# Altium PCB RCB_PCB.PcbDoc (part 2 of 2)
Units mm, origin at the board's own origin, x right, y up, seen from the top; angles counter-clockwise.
Board outline 360 x 80 mm, 2 copper layers (Top Layer, Bottom Layer); 41 components, 10 nets, 166 pads, 2592 vias.
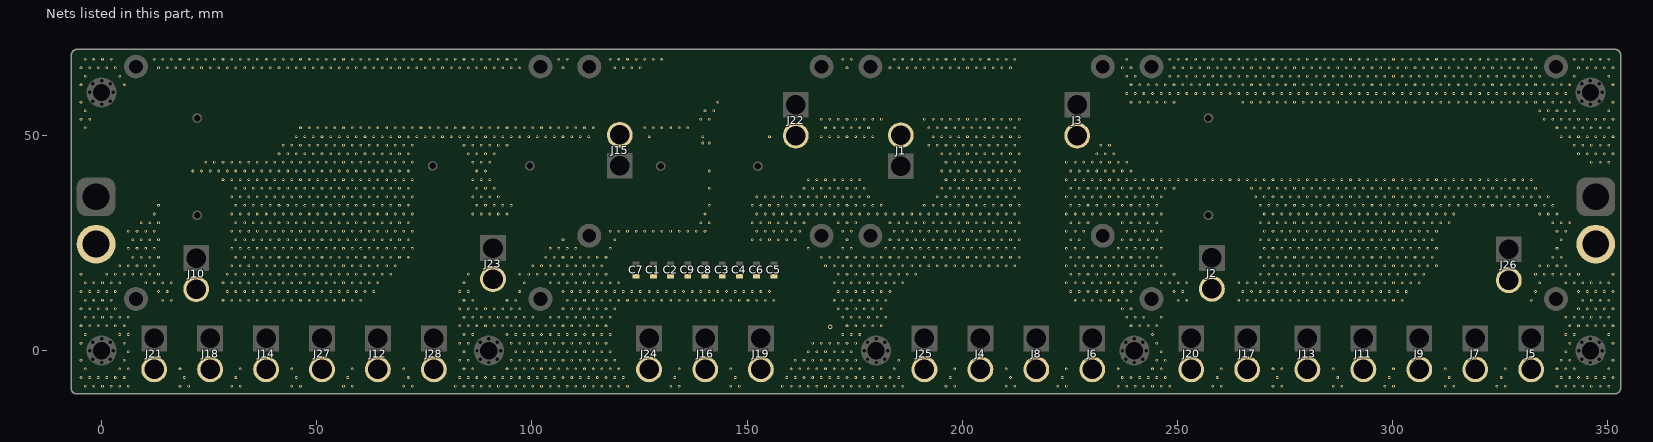
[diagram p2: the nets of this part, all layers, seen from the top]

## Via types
v1: diameter 0.6, hole 0.3, Top Layer to Bottom Layer, tented both sides, 2592 vias

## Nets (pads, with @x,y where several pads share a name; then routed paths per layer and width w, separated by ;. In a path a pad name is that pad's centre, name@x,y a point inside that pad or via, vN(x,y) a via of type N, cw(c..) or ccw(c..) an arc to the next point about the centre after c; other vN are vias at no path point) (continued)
GND: C1.2 C2.2 C3.2 C4.2 C5.2 C6.2 C7.2 C8.2 C9.2 J1.N J2.N J3.N J4.N J5.N J6.N J7.N J8.N J9.N J10.N J11.N J12.N J13.N J14.N J15.N J16.N J17.N J18.N J19.N J20.N J21.N J22.N J23.N J24.N J25.N J26.N J27.N J28.N pad.12 pad.N
  other v1: -3.769,-8.248 -1.769,-8.248 0.231,-8.248 2.231,-8.248 4.231,-8.248 6.231,-8.248 18.231,-8.248 20.231,-8.248 30.231,-8.248 32.231,-8.248 44.231,-8.248 46.231,-8.248 56.231,-8.248 58.231,-8.248 70.231,-8.248 72.231,-8.248 82.231,-8.248 84.231,-8.248 86.231,-8.248 88.231,-8.248 90.231,-8.248 92.231,-8.248 94.231,-8.248 96.231,-8.248 98.231,-8.248 100.231,-8.248 102.231,-8.248 104.231,-8.248 106.231,-8.248 108.231,-8.248 110.231,-8.248 112.231,-8.248 114.231,-8.248 116.231,-8.248 118.231,-8.248 120.231,-8.248 122.231,-8.248 132.231,-8.248 134.231,-8.248 146.231,-8.248 148.231,-8.248 158.231,-8.248 160.231,-8.248 162.231,-8.248 164.231,-8.248 166.231,-8.248 168.231,-8.248 170.231,-8.248 172.231,-8.248 174.231,-8.248 176.231,-8.248 178.231,-8.248 180.231,-8.248 182.231,-8.248 184.231,-8.248 186.231,-8.248 196.231,-8.248 198.231,-8.248 210.231,-8.248 212.231,-8.248 222.231,-8.248 224.231,-8.248 236.231,-8.248 238.231,-8.248 240.231,-8.248 242.231,-8.248 244.231,-8.248 246.231,-8.248 248.231,-8.248 258.231,-8.248 260.231,-8.248 272.231,-8.248 274.231,-8.248 286.231,-8.248 288.231,-8.248 298.231,-8.248 300.231,-8.248 312.231,-8.248 314.231,-8.248 324.231,-8.248 326.231,-8.248 338.231,-8.248 340.231,-8.248 342.231,-8.248 344.231,-8.248 346.231,-8.248 348.231,-8.248 350.231,-8.248 -4.769,-6.248 -2.769,-6.248 -0.769,-6.248 1.231,-6.248 3.231,-6.248 5.231,-6.248 19.231,-6.248 31.231,-6.248 45.231,-6.248 57.231,-6.248 71.231,-6.248 83.231,-6.248 85.231,-6.248 87.231,-6.248 89.231,-6.248 91.231,-6.248 93.231,-6.248 95.231,-6.248 97.231,-6.248 99.231,-6.248 101.231,-6.248 103.231,-6.248 105.231,-6.248 107.231,-6.248 109.231,-6.248 111.231,-6.248 113.231,-6.248 115.231,-6.248 117.231,-6.248 119.231,-6.248 121.231,-6.248 133.231,-6.248 147.231,-6.248 159.231,-6.248 161.231,-6.248 163.231,-6.248 165.231,-6.248 167.231,-6.248 169.231,-6.248 171.231,-6.248 173.231,-6.248 175.231,-6.248 177.231,-6.248 179.231,-6.248 181.231,-6.248 183.231,-6.248 185.231,-6.248 197.231,-6.248 211.231,-6.248 223.231,-6.248 237.231,-6.248 239.231,-6.248 241.231,-6.248 243.231,-6.248 245.231,-6.248 247.231,-6.248 259.231,-6.248 273.231,-6.248 287.231,-6.248 299.231,-6.248 313.231,-6.248 325.231,-6.248 339.231,-6.248 341.231,-6.248 343.231,-6.248 345.231,-6.248 347.231,-6.248 349.231,-6.248 351.231,-6.248 -3.769,-4.248 4.231,-4.248 6.231,-4.248 18.231,-4.248 32.231,-4.248 44.231,-4.248 58.231,-4.248 70.231,-4.248 84.231,-4.248 86.231,-4.248 94.231,-4.248 96.231,-4.248 98.231,-4.248 100.231,-4.248 102.231,-4.248 104.231,-4.248 106.231,-4.248 108.231,-4.248 110.231,-4.248 112.231,-4.248 114.231,-4.248 116.231,-4.248 118.231,-4.248 120.231,-4.248 134.231,-4.248 146.231,-4.248 160.231,-4.248 162.231,-4.248 164.231,-4.248 166.231,-4.248 168.231,-4.248 170.231,-4.248 172.231,-4.248 174.231,-4.248 176.231,-4.248 184.231,-4.248 198.231,-4.248 210.231,-4.248 224.231,-4.248 236.231,-4.248 244.231,-4.248 246.231,-4.248 260.231,-4.248 272.231,-4.248 274.231,-4.248 286.231,-4.248 300.231,-4.248 312.231,-4.248 326.231,-4.248 338.231,-4.248 340.231,-4.248 342.231,-4.248 350.231,-4.248 -4.769,-2.248 5.231,-2.248 83.231,-2.248 85.231,-2.248 95.231,-2.248 97.231,-2.248 99.231,-2.248 101.231,-2.248 103.231,-2.248 105.231,-2.248 107.231,-2.248 109.231,-2.248 111.231,-2.248 113.231,-2.248 115.231,-2.248 117.231,-2.248 119.231,-2.248 161.231,-2.248 163.231,-2.248 165.231,-2.248 167.231,-2.248 169.231,-2.248 171.231,-2.248 173.231,-2.248 175.231,-2.248 185.231,-2.248 245.231,-2.248 247.231,-2.248 339.231,-2.248 341.231,-2.248 351.231,-2.248 6.231,-0.248 84.231,-0.248 96.231,-0.248 98.231,-0.248 100.231,-0.248 102.231,-0.248 104.231,-0.248 106.231,-0.248 108.231,-0.248 110.231,-0.248 112.231,-0.248 114.231,-0.248 116.231,-0.248 118.231,-0.248 164.231,-0.248 166.231,-0.248 168.231,-0.248 170.231,-0.248 172.231,-0.248 174.231,-0.248 246.231,-0.248 340.231,-0.248 -4.769,1.752 5.231,1.752 83.231,1.752 85.231,1.752 95.231,1.752 97.231,1.752 99.231,1.752 101.231,1.752 103.231,1.752 105.231,1.752 107.231,1.752 109.231,1.752 111.231,1.752 113.231,1.752 115.231,1.752 117.231,1.752 165.231,1.752 167.231,1.752 169.231,1.752 171.231,1.752 173.231,1.752 175.231,1.752 245.231,1.752 341.231,1.752 351.231,1.752 -3.769,3.752 4.231,3.752 6.231,3.752 84.231,3.752 86.231,3.752 94.231,3.752 96.231,3.752 98.231,3.752 100.231,3.752 102.231,3.752 104.231,3.752 106.231,3.752 108.231,3.752 110.231,3.752 112.231,3.752 114.231,3.752 116.231,3.752 118.231,3.752 172.231,3.752 174.231,3.752 176.231,3.752 244.231,3.752 340.231,3.752 342.231,3.752 350.231,3.752 -4.769,5.752 -2.769,5.752 -0.769,5.752 1.231,5.752 3.231,5.752 5.231,5.752 83.231,5.752 85.231,5.752 87.231,5.752 89.231,5.752 91.231,5.752 93.231,5.752 95.231,5.752 97.231,5.752 99.231,5.752 101.231,5.752 103.231,5.752 105.231,5.752 107.231,5.752 109.231,5.752 111.231,5.752 113.231,5.752 115.231,5.752 117.231,5.752 173.231,5.752 175.231,5.752 177.231,5.752 179.231,5.752 181.231,5.752 239.231,5.752 241.231,5.752 243.231,5.752 245.231,5.752 341.231,5.752 343.231,5.752 345.231,5.752 347.231,5.752 349.231,5.752 351.231,5.752 -3.769,7.752 -1.769,7.752 0.231,7.752 2.231,7.752 4.231,7.752 6.231,7.752 84.231,7.752 86.231,7.752 88.231,7.752 90.231,7.752 92.231,7.752 94.231,7.752 96.231,7.752 98.231,7.752 100.231,7.752 104.231,7.752 106.231,7.752 108.231,7.752 110.231,7.752 112.231,7.752 114.231,7.752 116.231,7.752 118.231,7.752 172.231,7.752 174.231,7.752 176.231,7.752 178.231,7.752 180.231,7.752 182.231,7.752 238.231,7.752 240.231,7.752 242.231,7.752 246.231,7.752 340.231,7.752 342.231,7.752 344.231,7.752 346.231,7.752 348.231,7.752 350.231,7.752 -4.769,9.752 -2.769,9.752 -0.769,9.752 1.231,9.752 3.231,9.752 83.231,9.752 85.231,9.752 87.231,9.752 89.231,9.752 91.231,9.752 93.231,9.752 95.231,9.752 97.231,9.752 107.231,9.752 109.231,9.752 111.231,9.752 113.231,9.752 115.231,9.752 117.231,9.752 119.231,9.752 171.231,9.752 173.231,9.752 175.231,9.752 177.231,9.752 179.231,9.752 181.231,9.752 237.231,9.752 239.231,9.752 343.231,9.752 345.231,9.752 347.231,9.752 349.231,9.752 351.231,9.752 -3.769,11.752 -1.769,11.752 0.231,11.752 2.231,11.752 14.231,11.752 16.231,11.752 28.231,11.752 30.231,11.752 32.231,11.752 34.231,11.752 36.231,11.752 38.231,11.752 40.231,11.752 42.231,11.752 44.231,11.752 46.231,11.752 48.231,11.752 50.231,11.752 52.231,11.752 54.231,11.752 56.231,11.752 58.231,11.752 60.231,11.752 84.231,11.752 86.231,11.752 94.231,11.752 96.231,11.752 108.231,11.752 110.231,11.752 112.231,11.752 114.231,11.752 116.231,11.752 118.231,11.752 120.231,11.752 122.231,11.752 124.231,11.752 126.231,11.752 128.231,11.752 130.231,11.752 132.231,11.752 134.231,11.752 136.231,11.752 138.231,11.752 140.231,11.752 142.231,11.752 144.231,11.752 146.231,11.752 148.231,11.752 150.231,11.752 152.231,11.752 154.231,11.752 156.231,11.752 170.231,11.752 172.231,11.752 174.231,11.752 176.231,11.752 178.231,11.752 180.231,11.752 182.231,11.752 226.231,11.752 228.231,11.752 230.231,11.752 232.231,11.752 234.231,11.752 236.231,11.752 238.231,11.752 250.231,11.752 252.231,11.752 264.231,11.752 266.231,11.752 268.231,11.752 270.231,11.752 272.231,11.752 274.231,11.752 276.231,11.752 278.231,11.752 280.231,11.752 282.231,11.752 284.231,11.752 286.231,11.752 288.231,11.752 290.231,11.752 292.231,11.752 294.231,11.752 296.231,11.752 298.231,11.752 300.231,11.752 302.231,11.752 332.231,11.752 344.231,11.752 346.231,11.752 348.231,11.752 350.231,11.752 -4.769,13.752 -2.769,13.752 -0.769,13.752 1.231,13.752 3.231,13.752 13.231,13.752 15.231,13.752 29.231,13.752 31.231,13.752 33.231,13.752 35.231,13.752 37.231,13.752 39.231,13.752 41.231,13.752 43.231,13.752 45.231,13.752 47.231,13.752 49.231,13.752 51.231,13.752 53.231,13.752 55.231,13.752 57.231,13.752 59.231,13.752 61.231,13.752 63.231,13.752 83.231,13.752 85.231,13.752 97.231,13.752 107.231,13.752 109.231,13.752 111.231,13.752 113.231,13.752 115.231,13.752 117.231,13.752 119.231,13.752 121.231,13.752 123.231,13.752 125.231,13.752 127.231,13.752 129.231,13.752 131.231,13.752 133.231,13.752 135.231,13.752 137.231,13.752 139.231,13.752 141.231,13.752 143.231,13.752 145.231,13.752 147.231,13.752 149.231,13.752 151.231,13.752 153.231,13.752 155.231,13.752 171.231,13.752 173.231,13.752 175.231,13.752 177.231,13.752 179.231,13.752 181.231,13.752 183.231,13.752 225.231,13.752 227.231,13.752 229.231,13.752 231.231,13.752 233.231,13.752 235.231,13.752 237.231,13.752 239.231,13.752 249.231,13.752 251.231,13.752 265.231,13.752 267.231,13.752 269.231,13.752 271.231,13.752 273.231,13.752 275.231,13.752 277.231,13.752 279.231,13.752 281.231,13.752 283.231,13.752 285.231,13.752 287.231,13.752 289.231,13.752 291.231,13.752 293.231,13.752 295.231,13.752 297.231,13.752 299.231,13.752 301.231,13.752 303.231,13.752 333.231,13.752 343.231,13.752 345.231,13.752 347.231,13.752 349.231,13.752 351.231,13.752 -3.769,15.752 -1.769,15.752 0.231,15.752 2.231,15.752 4.231,15.752 10.231,15.752 12.231,15.752 14.231,15.752 16.231,15.752 28.231,15.752 30.231,15.752 32.231,15.752 34.231,15.752 36.231,15.752 38.231,15.752 40.231,15.752 42.231,15.752 44.231,15.752 46.231,15.752 48.231,15.752 50.231,15.752 52.231,15.752 54.231,15.752 56.231,15.752 58.231,15.752 60.231,15.752 62.231,15.752 64.231,15.752 84.231,15.752 98.231,15.752 104.231,15.752 106.231,15.752 108.231,15.752 110.231,15.752 112.231,15.752 114.231,15.752 116.231,15.752 118.231,15.752 120.231,15.752 170.231,15.752 172.231,15.752 174.231,15.752 176.231,15.752 178.231,15.752 180.231,15.752 182.231,15.752 184.231,15.752 186.231,15.752 224.231,15.752 226.231,15.752 228.231,15.752 230.231,15.752 232.231,15.752 234.231,15.752 236.231,15.752 238.231,15.752 240.231,15.752 246.231,15.752 248.231,15.752 250.231,15.752 252.231,15.752 264.231,15.752 266.231,15.752 268.231,15.752 270.231,15.752 272.231,15.752 274.231,15.752 276.231,15.752 278.231,15.752 280.231,15.752 282.231,15.752 284.231,15.752 286.231,15.752 288.231,15.752 290.231,15.752 292.231,15.752 294.231,15.752 296.231,15.752 298.231,15.752 300.231,15.752 302.231,15.752 304.231,15.752 306.231,15.752 334.231,15.752 340.231,15.752 342.231,15.752 344.231,15.752 346.231,15.752 348.231,15.752 350.231,15.752 -4.769,17.752 1.231,17.752 3.231,17.752 5.231,17.752 7.231,17.752 9.231,17.752 11.231,17.752 13.231,17.752 29.231,17.752 31.231,17.752 33.231,17.752 35.231,17.752 37.231,17.752 39.231,17.752 41.231,17.752 43.231,17.752 45.231,17.752 47.231,17.752 49.231,17.752 51.231,17.752 53.231,17.752 55.231,17.752 57.231,17.752 59.231,17.752 61.231,17.752 63.231,17.752 65.231,17.752 67.231,17.752 85.231,17.752 97.231,17.752 99.231,17.752 101.231,17.752 103.231,17.752 105.231,17.752 107.231,17.752 109.231,17.752 111.231,17.752 113.231,17.752 115.231,17.752 117.231,17.752 171.231,17.752 173.231,17.752 175.231,17.752 177.231,17.752 179.231,17.752 181.231,17.752 183.231,17.752 185.231,17.752 187.231,17.752 189.231,17.752 225.231,17.752 227.231,17.752 229.231,17.752 231.231,17.752 233.231,17.752 235.231,17.752 237.231,17.752 239.231,17.752 241.231,17.752 243.231,17.752 245.231,17.752 247.231,17.752 249.231,17.752 269.231,17.752 271.231,17.752 273.231,17.752 275.231,17.752 277.231,17.752 279.231,17.752 281.231,17.752 283.231,17.752 285.231,17.752 287.231,17.752 289.231,17.752 291.231,17.752 293.231,17.752 295.231,17.752 297.231,17.752 299.231,17.752 301.231,17.752 303.231,17.752 305.231,17.752 307.231,17.752 333.231,17.752 335.231,17.752 337.231,17.752 339.231,17.752 341.231,17.752 343.231,17.752 351.231,17.752 4.231,19.752 6.231,19.752 8.231,19.752 10.231,19.752 12.231,19.752 30.231,19.752 32.231,19.752 34.231,19.752 36.231,19.752 38.231,19.752 40.231,19.752 42.231,19.752 44.231,19.752 46.231,19.752 48.231,19.752 50.231,19.752 52.231,19.752 54.231,19.752 56.231,19.752 58.231,19.752 60.231,19.752 62.231,19.752 64.231,19.752 66.231,19.752 68.231,19.752 100.231,19.752 102.231,19.752 104.231,19.752 106.231,19.752 108.231,19.752 110.231,19.752 112.231,19.752 114.231,19.752 116.231,19.752 168.231,19.752 170.231,19.752 172.231,19.752 174.231,19.752 176.231,19.752 178.231,19.752 180.231,19.752 182.231,19.752 184.231,19.752 186.231,19.752 188.231,19.752 190.231,19.752 192.231,19.752 194.231,19.752 196.231,19.752 198.231,19.752 200.231,19.752 202.231,19.752 204.231,19.752 206.231,19.752 208.231,19.752 210.231,19.752 212.231,19.752 224.231,19.752 226.231,19.752 228.231,19.752 230.231,19.752 232.231,19.752 234.231,19.752 236.231,19.752 238.231,19.752 240.231,19.752 242.231,19.752 244.231,19.752 246.231,19.752 270.231,19.752 272.231,19.752 274.231,19.752 276.231,19.752 278.231,19.752 280.231,19.752 282.231,19.752 284.231,19.752 286.231,19.752 288.231,19.752 290.231,19.752 292.231,19.752 294.231,19.752 296.231,19.752 298.231,19.752 300.231,19.752 302.231,19.752 304.231,19.752 306.231,19.752 308.231,19.752 310.231,19.752 334.231,19.752 336.231,19.752 338.231,19.752 340.231,19.752 7.231,21.752 9.231,21.752 11.231,21.752 13.231,21.752 31.231,21.752 33.231,21.752 35.231,21.752 37.231,21.752 39.231,21.752 41.231,21.752 43.231,21.752 45.231,21.752 47.231,21.752 49.231,21.752 51.231,21.752 53.231,21.752 55.231,21.752 57.231,21.752 59.231,21.752 61.231,21.752 63.231,21.752 65.231,21.752 67.231,21.752 69.231,21.752 71.231,21.752 103.231,21.752 105.231,21.752 107.231,21.752 109.231,21.752 111.231,21.752 113.231,21.752 115.231,21.752 117.231,21.752 167.231,21.752 169.231,21.752 171.231,21.752 173.231,21.752 175.231,21.752 177.231,21.752 179.231,21.752 181.231,21.752 183.231,21.752 185.231,21.752 187.231,21.752 189.231,21.752 191.231,21.752 193.231,21.752 195.231,21.752 197.231,21.752 199.231,21.752 201.231,21.752 203.231,21.752 205.231,21.752 207.231,21.752 209.231,21.752 211.231,21.752 213.231,21.752 225.231,21.752 227.231,21.752 229.231,21.752 231.231,21.752 233.231,21.752 235.231,21.752 237.231,21.752 239.231,21.752 241.231,21.752 243.231,21.752 245.231,21.752 269.231,21.752 271.231,21.752 273.231,21.752 275.231,21.752 277.231,21.752 279.231,21.752 281.231,21.752 283.231,21.752 285.231,21.752 287.231,21.752 289.231,21.752 291.231,21.752 293.231,21.752 295.231,21.752 297.231,21.752 299.231,21.752 301.231,21.752 303.231,21.752 305.231,21.752 307.231,21.752 309.231,21.752 337.231,21.752 339.231,21.752 6.231,23.752 8.231,23.752 10.231,23.752 12.231,23.752 30.231,23.752 32.231,23.752 34.231,23.752 36.231,23.752 38.231,23.752 40.231,23.752 42.231,23.752 44.231,23.752 46.231,23.752 48.231,23.752 50.231,23.752 52.231,23.752 54.231,23.752 56.231,23.752 58.231,23.752 60.231,23.752 62.231,23.752 64.231,23.752 66.231,23.752 68.231,23.752 70.231,23.752 72.231,23.752 104.231,23.752 106.231,23.752 108.231,23.752 110.231,23.752 118.231,23.752 164.231,23.752 172.231,23.752 174.231,23.752 182.231,23.752 184.231,23.752 186.231,23.752 188.231,23.752 190.231,23.752 192.231,23.752 194.231,23.752 196.231,23.752 198.231,23.752 200.231,23.752 202.231,23.752 204.231,23.752 206.231,23.752 208.231,23.752 210.231,23.752 212.231,23.752 224.231,23.752 226.231,23.752 228.231,23.752 236.231,23.752 238.231,23.752 240.231,23.752 242.231,23.752 244.231,23.752 246.231,23.752 270.231,23.752 272.231,23.752 274.231,23.752 276.231,23.752 278.231,23.752 280.231,23.752 282.231,23.752 284.231,23.752 286.231,23.752 288.231,23.752 290.231,23.752 292.231,23.752 294.231,23.752 296.231,23.752 298.231,23.752 300.231,23.752 302.231,23.752 304.231,23.752 306.231,23.752 308.231,23.752 310.231,23.752 338.231,23.752 7.231,25.752 9.231,25.752 11.231,25.752 13.231,25.752 31.231,25.752 33.231,25.752 35.231,25.752 37.231,25.752 39.231,25.752 41.231,25.752 43.231,25.752 45.231,25.752 47.231,25.752 49.231,25.752 51.231,25.752 53.231,25.752 55.231,25.752 57.231,25.752 59.231,25.752 61.231,25.752 63.231,25.752 65.231,25.752 67.231,25.752 69.231,25.752 71.231,25.752 107.231,25.752 119.231,25.752 151.231,25.752 153.231,25.752 155.231,25.752 157.231,25.752 159.231,25.752 161.231,25.752 173.231,25.752 183.231,25.752 185.231,25.752 187.231,25.752 189.231,25.752 191.231,25.752 193.231,25.752 195.231,25.752 197.231,25.752 199.231,25.752 201.231,25.752 203.231,25.752 205.231,25.752 207.231,25.752 209.231,25.752 211.231,25.752 213.231,25.752 225.231,25.752 227.231,25.752 237.231,25.752 239.231,25.752 241.231,25.752 243.231,25.752 245.231,25.752 269.231,25.752 271.231,25.752 273.231,25.752 275.231,25.752 277.231,25.752 279.231,25.752 281.231,25.752 283.231,25.752 285.231,25.752 287.231,25.752 289.231,25.752 291.231,25.752 293.231,25.752 295.231,25.752 297.231,25.752 299.231,25.752 301.231,25.752 303.231,25.752 305.231,25.752 307.231,25.752 309.231,25.752 339.231,25.752 6.231,27.752 8.231,27.752 10.231,27.752 12.231,27.752 30.231,27.752 32.231,27.752 34.231,27.752 36.231,27.752 38.231,27.752 40.231,27.752 42.231,27.752 44.231,27.752 46.231,27.752 48.231,27.752 50.231,27.752 52.231,27.752 54.231,27.752 56.231,27.752 58.231,27.752 60.231,27.752 62.231,27.752 64.231,27.752 66.231,27.752 68.231,27.752 70.231,27.752 72.231,27.752 118.231,27.752 120.231,27.752 122.231,27.752 124.231,27.752 126.231,27.752 128.231,27.752 130.231,27.752 132.231,27.752 134.231,27.752 136.231,27.752 138.231,27.752 140.231,27.752 152.231,27.752 154.231,27.752 156.231,27.752 158.231,27.752 160.231,27.752 162.231,27.752 172.231,27.752 174.231,27.752 184.231,27.752 186.231,27.752 188.231,27.752 190.231,27.752 192.231,27.752 194.231,27.752 196.231,27.752 198.231,27.752 200.231,27.752 202.231,27.752 204.231,27.752 206.231,27.752 208.231,27.752 210.231,27.752 212.231,27.752 224.231,27.752 226.231,27.752 228.231,27.752 238.231,27.752 240.231,27.752 242.231,27.752 244.231,27.752 246.231,27.752 270.231,27.752 272.231,27.752 274.231,27.752 276.231,27.752 278.231,27.752 280.231,27.752 282.231,27.752 284.231,27.752 286.231,27.752 288.231,27.752 290.231,27.752 292.231,27.752 294.231,27.752 296.231,27.752 298.231,27.752 300.231,27.752 302.231,27.752 304.231,27.752 306.231,27.752 308.231,27.752 310.231,27.752 338.231,27.752 340.231,27.752 9.231,29.752 11.231,29.752 13.231,29.752 31.231,29.752 33.231,29.752 35.231,29.752 37.231,29.752 39.231,29.752 41.231,29.752 43.231,29.752 45.231,29.752 47.231,29.752 49.231,29.752 51.231,29.752 53.231,29.752 55.231,29.752 57.231,29.752 59.231,29.752 61.231,29.752 63.231,29.752 65.231,29.752 67.231,29.752 69.231,29.752 71.231,29.752 139.231,29.752 141.231,29.752 151.231,29.752 153.231,29.752 155.231,29.752 157.231,29.752 159.231,29.752 161.231,29.752 163.231,29.752 171.231,29.752 173.231,29.752 175.231,29.752 183.231,29.752 185.231,29.752 187.231,29.752 189.231,29.752 191.231,29.752 193.231,29.752 195.231,29.752 197.231,29.752 199.231,29.752 201.231,29.752 203.231,29.752 205.231,29.752 207.231,29.752 209.231,29.752 211.231,29.752 213.231,29.752 225.231,29.752 227.231,29.752 229.231,29.752 237.231,29.752 239.231,29.752 241.231,29.752 243.231,29.752 245.231,29.752 269.231,29.752 271.231,29.752 273.231,29.752 275.231,29.752 277.231,29.752 279.231,29.752 281.231,29.752 283.231,29.752 285.231,29.752 287.231,29.752 289.231,29.752 291.231,29.752 293.231,29.752 295.231,29.752 297.231,29.752 299.231,29.752 301.231,29.752 303.231,29.752 305.231,29.752 307.231,29.752 309.231,29.752 311.231,29.752 313.231,29.752 337.231,29.752 339.231,29.752 341.231,29.752 12.231,31.752 30.231,31.752 32.231,31.752 34.231,31.752 36.231,31.752 38.231,31.752 40.231,31.752 42.231,31.752 44.231,31.752 46.231,31.752 48.231,31.752 50.231,31.752 52.231,31.752 54.231,31.752 56.231,31.752 58.231,31.752 60.231,31.752 62.231,31.752 64.231,31.752 66.231,31.752 68.231,31.752 70.231,31.752 72.231,31.752 86.231,31.752 88.231,31.752 90.231,31.752 92.231,31.752 94.231,31.752 140.231,31.752 152.231,31.752 154.231,31.752 156.231,31.752 158.231,31.752 160.231,31.752 162.231,31.752 164.231,31.752 166.231,31.752 168.231,31.752 170.231,31.752 172.231,31.752 174.231,31.752 176.231,31.752 178.231,31.752 180.231,31.752 182.231,31.752 184.231,31.752 186.231,31.752 188.231,31.752 190.231,31.752 192.231,31.752 194.231,31.752 196.231,31.752 198.231,31.752 200.231,31.752 202.231,31.752 204.231,31.752 206.231,31.752 208.231,31.752 210.231,31.752 212.231,31.752 224.231,31.752 226.231,31.752 228.231,31.752 230.231,31.752 232.231,31.752 234.231,31.752 236.231,31.752 238.231,31.752 240.231,31.752 242.231,31.752 244.231,31.752 246.231,31.752 270.231,31.752 272.231,31.752 274.231,31.752 276.231,31.752 278.231,31.752 280.231,31.752 282.231,31.752 284.231,31.752 286.231,31.752 288.231,31.752 290.231,31.752 292.231,31.752 294.231,31.752 296.231,31.752 298.231,31.752 300.231,31.752 302.231,31.752 304.231,31.752 306.231,31.752 308.231,31.752 310.231,31.752 312.231,31.752 314.231,31.752 334.231,31.752 336.231,31.752 338.231,31.752 13.231,33.752 31.231,33.752 33.231,33.752 35.231,33.752 37.231,33.752 39.231,33.752 41.231,33.752 43.231,33.752 45.231,33.752 47.231,33.752 49.231,33.752 51.231,33.752 53.231,33.752 55.231,33.752 57.231,33.752 59.231,33.752 61.231,33.752 63.231,33.752 65.231,33.752 67.231,33.752 69.231,33.752 71.231,33.752 87.231,33.752 89.231,33.752 91.231,33.752 93.231,33.752 95.231,33.752 141.231,33.752 151.231,33.752 153.231,33.752 155.231,33.752 157.231,33.752 159.231,33.752 161.231,33.752 163.231,33.752 165.231,33.752 167.231,33.752 169.231,33.752 171.231,33.752 173.231,33.752 175.231,33.752 177.231,33.752 179.231,33.752 181.231,33.752 191.231,33.752 193.231,33.752 195.231,33.752 197.231,33.752 199.231,33.752 201.231,33.752 203.231,33.752 205.231,33.752 207.231,33.752 209.231,33.752 211.231,33.752 213.231,33.752 225.231,33.752 227.231,33.752 229.231,33.752 231.231,33.752 233.231,33.752 235.231,33.752 237.231,33.752 239.231,33.752 241.231,33.752 243.231,33.752 245.231,33.752 269.231,33.752 271.231,33.752 273.231,33.752 275.231,33.752 277.231,33.752 279.231,33.752 281.231,33.752 283.231,33.752 285.231,33.752 287.231,33.752 289.231,33.752 291.231,33.752 293.231,33.752 295.231,33.752 297.231,33.752 299.231,33.752 301.231,33.752 303.231,33.752 305.231,33.752 307.231,33.752 309.231,33.752 311.231,33.752 313.231,33.752 315.231,33.752 317.231,33.752 319.231,33.752 321.231,33.752 323.231,33.752 325.231,33.752 327.231,33.752 329.231,33.752 331.231,33.752 333.231,33.752 335.231,33.752 337.231,33.752 30.231,35.752 32.231,35.752 34.231,35.752 36.231,35.752 38.231,35.752 40.231,35.752 42.231,35.752 44.231,35.752 46.231,35.752 48.231,35.752 50.231,35.752 52.231,35.752 54.231,35.752 56.231,35.752 58.231,35.752 60.231,35.752 62.231,35.752 64.231,35.752 66.231,35.752 68.231,35.752 70.231,35.752 72.231,35.752 86.231,35.752 88.231,35.752 90.231,35.752 92.231,35.752 152.231,35.752 154.231,35.752 156.231,35.752 158.231,35.752 160.231,35.752 162.231,35.752 164.231,35.752 166.231,35.752 168.231,35.752 170.231,35.752 172.231,35.752 174.231,35.752 176.231,35.752 178.231,35.752 194.231,35.752 196.231,35.752 198.231,35.752 200.231,35.752 202.231,35.752 204.231,35.752 206.231,35.752 208.231,35.752 210.231,35.752 212.231,35.752 224.231,35.752 226.231,35.752 228.231,35.752 230.231,35.752 232.231,35.752 234.231,35.752 236.231,35.752 238.231,35.752 240.231,35.752 242.231,35.752 244.231,35.752 246.231,35.752 268.231,35.752 270.231,35.752 272.231,35.752 274.231,35.752 276.231,35.752 278.231,35.752 280.231,35.752 282.231,35.752 284.231,35.752 286.231,35.752 288.231,35.752 290.231,35.752 292.231,35.752 294.231,35.752 296.231,35.752 298.231,35.752 300.231,35.752 302.231,35.752 304.231,35.752 306.231,35.752 308.231,35.752 310.231,35.752 312.231,35.752 314.231,35.752 316.231,35.752 318.231,35.752 320.231,35.752 322.231,35.752 324.231,35.752 326.231,35.752 328.231,35.752 330.231,35.752 332.231,35.752 334.231,35.752 336.231,35.752 31.231,37.752 33.231,37.752 35.231,37.752 37.231,37.752 39.231,37.752 41.231,37.752 43.231,37.752 45.231,37.752 47.231,37.752 49.231,37.752 51.231,37.752 53.231,37.752 55.231,37.752 57.231,37.752 59.231,37.752 61.231,37.752 63.231,37.752 65.231,37.752 67.231,37.752 69.231,37.752 71.231,37.752 87.231,37.752 89.231,37.752 91.231,37.752 141.231,37.752 163.231,37.752 165.231,37.752 167.231,37.752 169.231,37.752 171.231,37.752 173.231,37.752 175.231,37.752 177.231,37.752 195.231,37.752 197.231,37.752 199.231,37.752 201.231,37.752 203.231,37.752 205.231,37.752 207.231,37.752 209.231,37.752 211.231,37.752 213.231,37.752 225.231,37.752 227.231,37.752 229.231,37.752 231.231,37.752 233.231,37.752 235.231,37.752 237.231,37.752 239.231,37.752 241.231,37.752 243.231,37.752 245.231,37.752 247.231,37.752 249.231,37.752 267.231,37.752 269.231,37.752 271.231,37.752 273.231,37.752 275.231,37.752 277.231,37.752 279.231,37.752 281.231,37.752 283.231,37.752 285.231,37.752 287.231,37.752 289.231,37.752 291.231,37.752 293.231,37.752 295.231,37.752 297.231,37.752 299.231,37.752 301.231,37.752 303.231,37.752 305.231,37.752 307.231,37.752 309.231,37.752 311.231,37.752 313.231,37.752 315.231,37.752 317.231,37.752 319.231,37.752 321.231,37.752 323.231,37.752 325.231,37.752 327.231,37.752 329.231,37.752 331.231,37.752 333.231,37.752 28.231,39.752 30.231,39.752 32.231,39.752 34.231,39.752 36.231,39.752 38.231,39.752 40.231,39.752 42.231,39.752 44.231,39.752 46.231,39.752 48.231,39.752 50.231,39.752 52.231,39.752 54.231,39.752 56.231,39.752 58.231,39.752 60.231,39.752 62.231,39.752 64.231,39.752 66.231,39.752 68.231,39.752 70.231,39.752 72.231,39.752 86.231,39.752 88.231,39.752 90.231,39.752 164.231,39.752 166.231,39.752 168.231,39.752 170.231,39.752 172.231,39.752 174.231,39.752 176.231,39.752 196.231,39.752 198.231,39.752 200.231,39.752 202.231,39.752 204.231,39.752 206.231,39.752 208.231,39.752 210.231,39.752 212.231,39.752 224.231,39.752 226.231,39.752 228.231,39.752 230.231,39.752 232.231,39.752 234.231,39.752 236.231,39.752 238.231,39.752 240.231,39.752 242.231,39.752 244.231,39.752 246.231,39.752 248.231,39.752 250.231,39.752 252.231,39.752 254.231,39.752 256.231,39.752 258.231,39.752 260.231,39.752 262.231,39.752 264.231,39.752 266.231,39.752 268.231,39.752 270.231,39.752 272.231,39.752 274.231,39.752 276.231,39.752 278.231,39.752 280.231,39.752 282.231,39.752 284.231,39.752 286.231,39.752 288.231,39.752 290.231,39.752 292.231,39.752 294.231,39.752 296.231,39.752 298.231,39.752 300.231,39.752 302.231,39.752 304.231,39.752 306.231,39.752 308.231,39.752 310.231,39.752 312.231,39.752 314.231,39.752 316.231,39.752 318.231,39.752 320.231,39.752 322.231,39.752 324.231,39.752 326.231,39.752 328.231,39.752 330.231,39.752 332.231,39.752 21.231,41.752 23.231,41.752 25.231,41.752 27.231,41.752 29.231,41.752 31.231,41.752 33.231,41.752 35.231,41.752 37.231,41.752 39.231,41.752 41.231,41.752 43.231,41.752 45.231,41.752 47.231,41.752 49.231,41.752 51.231,41.752 53.231,41.752 55.231,41.752 57.231,41.752 59.231,41.752 61.231,41.752 63.231,41.752 65.231,41.752 67.231,41.752 69.231,41.752 71.231,41.752 87.231,41.752 89.231,41.752 141.231,41.752 195.231,41.752 197.231,41.752 199.231,41.752 201.231,41.752 203.231,41.752 205.231,41.752 207.231,41.752 209.231,41.752 211.231,41.752 213.231,41.752 225.231,41.752 227.231,41.752 229.231,41.752 231.231,41.752 233.231,41.752 235.231,41.752 237.231,41.752 239.231,41.752 24.231,43.752 26.231,43.752 28.231,43.752 30.231,43.752 32.231,43.752 34.231,43.752 36.231,43.752 38.231,43.752 40.231,43.752 42.231,43.752 44.231,43.752 46.231,43.752 48.231,43.752 50.231,43.752 52.231,43.752 54.231,43.752 56.231,43.752 58.231,43.752 60.231,43.752 62.231,43.752 64.231,43.752 66.231,43.752 68.231,43.752 70.231,43.752 72.231,43.752 86.231,43.752 88.231,43.752 90.231,43.752 196.231,43.752 198.231,43.752 200.231,43.752 202.231,43.752 204.231,43.752 206.231,43.752 208.231,43.752 210.231,43.752 212.231,43.752 224.231,43.752 226.231,43.752 228.231,43.752 230.231,43.752 232.231,43.752 234.231,43.752 236.231,43.752 238.231,43.752 346.231,43.752 348.231,43.752 350.231,43.752 41.231,45.752 43.231,45.752 45.231,45.752 47.231,45.752 49.231,45.752 51.231,45.752 53.231,45.752 55.231,45.752 57.231,45.752 59.231,45.752 61.231,45.752 63.231,45.752 65.231,45.752 67.231,45.752 69.231,45.752 71.231,45.752 85.231,45.752 87.231,45.752 89.231,45.752 91.231,45.752 195.231,45.752 197.231,45.752 199.231,45.752 201.231,45.752 203.231,45.752 205.231,45.752 207.231,45.752 209.231,45.752 211.231,45.752 213.231,45.752 231.231,45.752 233.231,45.752 235.231,45.752 343.231,45.752 345.231,45.752 347.231,45.752 349.231,45.752 351.231,45.752 42.231,47.752 44.231,47.752 46.231,47.752 48.231,47.752 50.231,47.752 52.231,47.752 54.231,47.752 56.231,47.752 58.231,47.752 60.231,47.752 62.231,47.752 64.231,47.752 66.231,47.752 68.231,47.752 70.231,47.752 72.231,47.752 84.231,47.752 86.231,47.752 88.231,47.752 90.231,47.752 92.231,47.752 94.231,47.752 192.231,47.752 194.231,47.752 196.231,47.752 198.231,47.752 200.231,47.752 202.231,47.752 204.231,47.752 206.231,47.752 208.231,47.752 210.231,47.752 212.231,47.752 232.231,47.752 234.231,47.752 342.231,47.752 344.231,47.752 346.231,47.752 348.231,47.752 350.231,47.752 139.731,48.252 141.231,48.252 45.231,49.752 47.231,49.752 49.231,49.752 51.231,49.752 53.231,49.752 55.231,49.752 57.231,49.752 59.231,49.752 61.231,49.752 63.231,49.752 65.231,49.752 67.231,49.752 69.231,49.752 71.231,49.752 73.231,49.752 75.231,49.752 77.231,49.752 79.231,49.752 81.231,49.752 83.231,49.752 85.231,49.752 87.231,49.752 89.231,49.752 91.231,49.752 93.231,49.752 95.231,49.752 97.231,49.752 99.231,49.752 101.231,49.752 103.231,49.752 105.231,49.752 107.231,49.752 109.231,49.752 111.231,49.752 113.231,49.752 127.231,49.752 139.731,49.752 155.231,49.752 167.231,49.752 169.231,49.752 171.231,49.752 173.231,49.752 175.231,49.752 177.231,49.752 179.231,49.752 193.231,49.752 195.231,49.752 197.231,49.752 199.231,49.752 201.231,49.752 203.231,49.752 205.231,49.752 207.231,49.752 209.231,49.752 211.231,49.752 213.231,49.752 339.231,49.752 341.231,49.752 343.231,49.752 345.231,49.752 347.231,49.752 349.231,49.752 351.231,49.752 -3.769,51.752 46.231,51.752 48.231,51.752 50.231,51.752 52.231,51.752 54.231,51.752 56.231,51.752 58.231,51.752 60.231,51.752 62.231,51.752 64.231,51.752 66.231,51.752 68.231,51.752 70.231,51.752 72.231,51.752 74.231,51.752 76.231,51.752 78.231,51.752 80.231,51.752 82.231,51.752 84.231,51.752 86.231,51.752 88.231,51.752 90.231,51.752 92.231,51.752 94.231,51.752 96.231,51.752 98.231,51.752 100.231,51.752 102.231,51.752 104.231,51.752 106.231,51.752 108.231,51.752 110.231,51.752 112.231,51.752 114.231,51.752 126.231,51.752 128.231,51.752 130.231,51.752 132.231,51.752 134.231,51.752 136.231,51.752 168.231,51.752 170.231,51.752 172.231,51.752 174.231,51.752 176.231,51.752 178.231,51.752 192.231,51.752 194.231,51.752 196.231,51.752 198.231,51.752 200.231,51.752 202.231,51.752 204.231,51.752 206.231,51.752 208.231,51.752 210.231,51.752 212.231,51.752 338.231,51.752 340.231,51.752 342.231,51.752 344.231,51.752 346.231,51.752 348.231,51.752 350.231,51.752 -4.769,53.752 -2.769,53.752 139.231,53.752 141.231,53.752 167.231,53.752 169.231,53.752 171.231,53.752 173.231,53.752 175.231,53.752 177.231,53.752 179.231,53.752 181.231,53.752 191.231,53.752 193.231,53.752 195.231,53.752 197.231,53.752 199.231,53.752 201.231,53.752 203.231,53.752 205.231,53.752 207.231,53.752 209.231,53.752 211.231,53.752 213.231,53.752 335.231,53.752 337.231,53.752 339.231,53.752 341.231,53.752 343.231,53.752 345.231,53.752 347.231,53.752 349.231,53.752 351.231,53.752 -3.769,55.752 140.231,55.752 142.231,55.752 334.231,55.752 336.231,55.752 338.231,55.752 340.231,55.752 342.231,55.752 350.231,55.752 -4.769,57.752 143.231,57.752 239.231,57.752 241.231,57.752 243.231,57.752 245.231,57.752 247.231,57.752 249.231,57.752 265.231,57.752 267.231,57.752 269.231,57.752 271.231,57.752 273.231,57.752 275.231,57.752 277.231,57.752 279.231,57.752 281.231,57.752 283.231,57.752 285.231,57.752 287.231,57.752 289.231,57.752 291.231,57.752 293.231,57.752 295.231,57.752 297.231,57.752 299.231,57.752 301.231,57.752 303.231,57.752 305.231,57.752 307.231,57.752 309.231,57.752 311.231,57.752 313.231,57.752 315.231,57.752 317.231,57.752 319.231,57.752 321.231,57.752 323.231,57.752 325.231,57.752 327.231,57.752 329.231,57.752 331.231,57.752 333.231,57.752 335.231,57.752 337.231,57.752 339.231,57.752 341.231,57.752 351.231,57.752 238.231,59.752 240.231,59.752 242.231,59.752 244.231,59.752 246.231,59.752 248.231,59.752 250.231,59.752 252.231,59.752 254.231,59.752 256.231,59.752 258.231,59.752 260.231,59.752 262.231,59.752 264.231,59.752 266.231,59.752 268.231,59.752 270.231,59.752 272.231,59.752 274.231,59.752 276.231,59.752 278.231,59.752 280.231,59.752 282.231,59.752 284.231,59.752 286.231,59.752 288.231,59.752 290.231,59.752 292.231,59.752 294.231,59.752 296.231,59.752 298.231,59.752 300.231,59.752 302.231,59.752 304.231,59.752 306.231,59.752 308.231,59.752 310.231,59.752 312.231,59.752 314.231,59.752 316.231,59.752 318.231,59.752 320.231,59.752 322.231,59.752 324.231,59.752 326.231,59.752 328.231,59.752 330.231,59.752 332.231,59.752 334.231,59.752 336.231,59.752 338.231,59.752 340.231,59.752 -4.769,61.752 5.231,61.752 239.231,61.752 241.231,61.752 243.231,61.752 245.231,61.752 247.231,61.752 249.231,61.752 251.231,61.752 253.231,61.752 255.231,61.752 257.231,61.752 259.231,61.752 261.231,61.752 263.231,61.752 265.231,61.752 267.231,61.752 269.231,61.752 271.231,61.752 273.231,61.752 275.231,61.752 277.231,61.752 279.231,61.752 281.231,61.752 283.231,61.752 285.231,61.752 287.231,61.752 289.231,61.752 291.231,61.752 293.231,61.752 295.231,61.752 297.231,61.752 299.231,61.752 301.231,61.752 303.231,61.752 305.231,61.752 307.231,61.752 309.231,61.752 311.231,61.752 313.231,61.752 315.231,61.752 317.231,61.752 319.231,61.752 321.231,61.752 323.231,61.752 325.231,61.752 327.231,61.752 329.231,61.752 331.231,61.752 333.231,61.752 335.231,61.752 337.231,61.752 339.231,61.752 341.231,61.752 351.231,61.752 -3.769,63.752 4.231,63.752 238.231,63.752 240.231,63.752 248.231,63.752 250.231,63.752 252.231,63.752 254.231,63.752 256.231,63.752 258.231,63.752 260.231,63.752 262.231,63.752 264.231,63.752 266.231,63.752 268.231,63.752 270.231,63.752 272.231,63.752 274.231,63.752 276.231,63.752 278.231,63.752 280.231,63.752 282.231,63.752 284.231,63.752 286.231,63.752 288.231,63.752 290.231,63.752 292.231,63.752 294.231,63.752 296.231,63.752 298.231,63.752 300.231,63.752 302.231,63.752 304.231,63.752 306.231,63.752 308.231,63.752 310.231,63.752 312.231,63.752 314.231,63.752 316.231,63.752 318.231,63.752 320.231,63.752 322.231,63.752 324.231,63.752 326.231,63.752 328.231,63.752 330.231,63.752 332.231,63.752 334.231,63.752 342.231,63.752 350.231,63.752 -4.769,65.752 -2.769,65.752 -0.769,65.752 1.231,65.752 3.231,65.752 13.231,65.752 15.231,65.752 17.231,65.752 19.231,65.752 21.231,65.752 23.231,65.752 25.231,65.752 27.231,65.752 29.231,65.752 31.231,65.752 33.231,65.752 35.231,65.752 37.231,65.752 39.231,65.752 41.231,65.752 43.231,65.752 45.231,65.752 47.231,65.752 49.231,65.752 51.231,65.752 53.231,65.752 55.231,65.752 57.231,65.752 59.231,65.752 61.231,65.752 63.231,65.752 65.231,65.752 67.231,65.752 69.231,65.752 71.231,65.752 73.231,65.752 75.231,65.752 77.231,65.752 79.231,65.752 81.231,65.752 83.231,65.752 85.231,65.752 87.231,65.752 89.231,65.752 91.231,65.752 93.231,65.752 95.231,65.752 97.231,65.752 107.231,65.752 119.231,65.752 121.231,65.752 123.231,65.752 125.231,65.752 173.231,65.752 183.231,65.752 185.231,65.752 187.231,65.752 189.231,65.752 191.231,65.752 193.231,65.752 195.231,65.752 197.231,65.752 199.231,65.752 201.231,65.752 203.231,65.752 205.231,65.752 207.231,65.752 209.231,65.752 211.231,65.752 237.231,65.752 239.231,65.752 249.231,65.752 251.231,65.752 253.231,65.752 255.231,65.752 257.231,65.752 259.231,65.752 261.231,65.752 263.231,65.752 265.231,65.752 267.231,65.752 269.231,65.752 271.231,65.752 273.231,65.752 275.231,65.752 277.231,65.752 279.231,65.752 281.231,65.752 283.231,65.752 285.231,65.752 287.231,65.752 289.231,65.752 291.231,65.752 293.231,65.752 295.231,65.752 297.231,65.752 299.231,65.752 301.231,65.752 303.231,65.752 305.231,65.752 307.231,65.752 309.231,65.752 311.231,65.752 313.231,65.752 315.231,65.752 317.231,65.752 319.231,65.752 321.231,65.752 323.231,65.752 325.231,65.752 327.231,65.752 329.231,65.752 331.231,65.752 333.231,65.752 343.231,65.752 345.231,65.752 347.231,65.752 349.231,65.752 351.231,65.752 -3.769,67.752 -1.769,67.752 0.231,67.752 2.231,67.752 12.231,67.752 14.231,67.752 16.231,67.752 18.231,67.752 20.231,67.752 22.231,67.752 24.231,67.752 26.231,67.752 28.231,67.752 30.231,67.752 32.231,67.752 34.231,67.752 36.231,67.752 38.231,67.752 40.231,67.752 42.231,67.752 44.231,67.752 46.231,67.752 48.231,67.752 50.231,67.752 52.231,67.752 54.231,67.752 56.231,67.752 58.231,67.752 60.231,67.752 62.231,67.752 64.231,67.752 66.231,67.752 68.231,67.752 70.231,67.752 72.231,67.752 74.231,67.752 76.231,67.752 78.231,67.752 80.231,67.752 82.231,67.752 84.231,67.752 86.231,67.752 88.231,67.752 90.231,67.752 92.231,67.752 94.231,67.752 96.231,67.752 106.231,67.752 108.231,67.752 118.231,67.752 120.231,67.752 122.231,67.752 124.231,67.752 126.231,67.752 128.231,67.752 130.231,67.752 172.231,67.752 174.231,67.752 184.231,67.752 186.231,67.752 188.231,67.752 190.231,67.752 192.231,67.752 194.231,67.752 196.231,67.752 198.231,67.752 200.231,67.752 202.231,67.752 204.231,67.752 206.231,67.752 208.231,67.752 210.231,67.752 212.231,67.752 238.231,67.752 248.231,67.752 250.231,67.752 252.231,67.752 254.231,67.752 256.231,67.752 258.231,67.752 260.231,67.752 262.231,67.752 264.231,67.752 266.231,67.752 268.231,67.752 270.231,67.752 272.231,67.752 274.231,67.752 276.231,67.752 278.231,67.752 280.231,67.752 282.231,67.752 284.231,67.752 286.231,67.752 288.231,67.752 290.231,67.752 292.231,67.752 294.231,67.752 296.231,67.752 298.231,67.752 300.231,67.752 302.231,67.752 304.231,67.752 306.231,67.752 308.231,67.752 310.231,67.752 312.231,67.752 314.231,67.752 316.231,67.752 318.231,67.752 320.231,67.752 322.231,67.752 324.231,67.752 326.231,67.752 328.231,67.752 330.231,67.752 332.231,67.752 342.231,67.752 344.231,67.752 346.231,67.752 348.231,67.752 350.231,67.752

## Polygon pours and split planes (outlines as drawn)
GND on Top Layer "GND_L01_P063" (solid, pour order 63): -6,-10 cw(c-6,-9) -7,-9 -7,69 cw(c-6,69) -6,70 352,70 cw(c352,69) 353,69 353,-9 cw(c352,-9) 352,-10
42V_IN on Top Layer "Top Layer-42V_IN" (solid, pour order 59): 173,56.25 173.5,56.75 213.5,56.75 218,61.25 229.5,61.25 231,59.75 231,53.25 242.25,42 333,42 341.25,33.75 341.25,32 342.75,30.5 351,30.5 352.5,32 352.5,41 351.5,42 344.25,42 331.75,54.5 266,54.5 263.5,57 251.25,57 248.75,54.5 240.021,54.5 236.5,58.021 236.5,61.5 235,63 231.25,63 229.5,64.75 229.5,66.5 228.25,67.75 215.5,67.75 210,62.25 173,62.25 172.5,62.75 167,62.75 166.5,62.75 166.25,62.75 164,64.795 164,66.25 163,67.25 133.75,67.25 131.252,64.752 127.502,64.752 125.002,62.252 9.731,62.252 -6.269,46.252 -6.269,31.752 -4.769,30.252 6.731,30.252 22.731,46.252 38.502,46.252 46.75,54.5 136,54.5 142.5,61 164.5,61 165.5,60 165.5,56.75 166,56.25 166.5,55.75 172.5,55.75
12VOUT on Top Layer "12VOUT_L01_P053" (solid, pour order 53): 229.75,60.25 229.75,54 229.25,53.5 223.75,53.5 222,51.75 222,13.75 226,9.75 234.75,9.75 235.75,8.75 235.75,-0.25 235,-1 186.5,-1 184.25,1.25 184.25,10.75 189.75,16.25 214.5,16.25 215.5,17.25 215.5,55.25 221,60.75 229,60.75
42V_IN on Top Layer "42V_IN_L01_P051" (solid, pour order 51): 165.5,60 165.5,58.75 166,58.25 167.5,58.25 167.5,60.5 167,61 165.75,61
24VOUT on Top Layer "Top Layer-24VOUT" (solid, pour order 49): 7.75,0 8.5,-1 80.25,-1 81.5,0.25 81.5,17.25 84.25,20 100.25,20 109.25,29 110.5,30.25 136.5,30.25 139.25,33 139.25,46.75 136.75,49.25 129,49.25 127,47.25 127,35 126.5,34.5 98.75,34.5 96,31.75 96,28.5 86.5,28.5 84,31 84,44.25 81.5,46.75 74,46.75 74,22.25 66.75,15 60.75,9 9.75,9 7.75,7 7.75,0.25
5VOUT on Top Layer "5VOUT_L01_P035" (solid, pour order 35): 249.065,-0.75 336.729,-0.75 338.231,0.752 338.231,6.252 335.231,9.252 324.998,9.252 320.231,14.019 320.231,17.752 322.231,19.752 331.731,19.752 335.731,23.752 335.731,28.252 333.731,30.252 316.231,30.252 312.731,26.752 312.731,19.731 303,10 250.479,10 247.731,7.252 247.731,1.252
5VIN on Top Layer "5VIN_L01_P034" (solid, pour order 34): 251.731,37.752 248.731,34.752 248.731,20.752 251.731,17.752 265.231,17.752 266.731,19.252 266.731,35.252 264.231,37.752
12VIN on Top Layer "12VIN_L01_P033" (solid, pour order 33): 152.231,46.752 150.231,44.752 150.231,40.252 151.731,38.752 160.731,38.752 164.731,42.752 175.731,42.752 179.231,39.252 179.231,37.752 181.731,35.252 190.231,35.252 193.231,38.252 193.231,44.252 190.731,46.752 176.731,46.752 176.231,46.252 156.731,46.252 156.231,46.752
19v5VOUT on Top Layer "Top Layer-19v5VOUT" (solid, pour order 27): 119.731,19.252 120.231,18.752 158.231,18.752 158.231,9.752 157.731,9.252 122.231,9.252 120.731,7.752 120.731,0.752 121.606,-1 159.979,-1 167.731,6.752 167.731,17.752 163.231,22.252 151.731,22.252 149.231,24.752 149.231,47.752 154.731,53.252 164.231,53.252 164.75,53.771 164.75,60.25 149,60.25 143.231,54.481 143.231,25.752 142.731,25.252 122.731,25.252 119.731,22.252
19v5VIN on Top Layer "19V5VIN_L01_P019" (solid, pour order 19): 123.231,46.752 96.231,46.752 92.731,43.252 92.731,38.252 94.231,36.752 123.231,36.752 125.231,38.752 125.231,45.752
24VIN on Top Layer "24VIN_L01_P017" (solid, pour order 17): 16.731,17.752 26.731,17.752 28.231,19.252 28.231,37.252 26.231,39.252 17.731,39.252 15.25,36.771 15.25,18.936
GND on Bottom Layer "GND_L02_P062" (solid, pour order 62): -6,-10 cw(c-6,-9) -7,-9 -7,69 cw(c-6,69) -6,70 352,70 cw(c352,69) 353,69 353,-9 cw(c352,-9) 352,-10

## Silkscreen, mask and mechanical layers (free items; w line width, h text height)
Top Overlay:
  drawing of 78 lines, arcs and shapes, not listed
  text "42VIN" at -6.269,42.266 h5
  text "42VIN" at 342.231,42.266 h5
  text "24V OUTPUT" at 34.121,10.989 h5
  text "5V OUTPUT" at 283.149,10.989 h5
  text "19.5V OUTPUT" at 128.129,10.239 h5
  text "12V OUTPUT" at 200.184,10.239 h5
  text "RCB" at 343.985,-6.994 h1.52
  text "19.5" at 131.831,-7.212 h3
  text "19.5" at 144.902,-7.212 h3
  text "5" at 258.731,-7.711 h5
  text "5" at 271.731,-7.711 h5
  text "5" at 285.731,-7.711 h5
  text "5" at 298.731,-7.711 h5
  text "5" at 311.731,-7.711 h5
  text "5" at 324.731,-7.711 h5
  text "24" at 16.881,-7.741 h5
  text "24" at 29.881,-7.741 h5
  text "24" at 42.881,-7.741 h5
  text "24" at 55.881,-7.741 h5
  text "24" at 68.881,-7.741 h5
  text "12" at 195.981,-7.748 h5
  text "12" at 208.981,-7.748 h5
  text "12" at 221.981,-7.748 h5
Bottom Overlay:
  text "Hani Benim RCB'm" at 118.981,-0.998 h1.5
  text "04.2025" at 350.977,-6.994 h1.52
Mechanical 1:
  lines w0.2: 240.993,70 340.993,70 ; -7,-8.941 ccw(c-5.941,-8.941) -5.941,-10 347,-10 351.73,-10 ccw(c351.73,-8.73) 353,-8.73 353,-7.73 353,-3 353,63 353,67.73 353,68.73 ccw(c351.73,68.73) 351.73,70 347,70 -1,70 -5.73,70 ccw(c-5.73,68.73) -7,68.73 -7,67.73 -7,63 -7,-3 -7,-7.73 -7,-8.941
